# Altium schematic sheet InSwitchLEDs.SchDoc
size A4; SheetNumber: 2; SheetTotal: 2
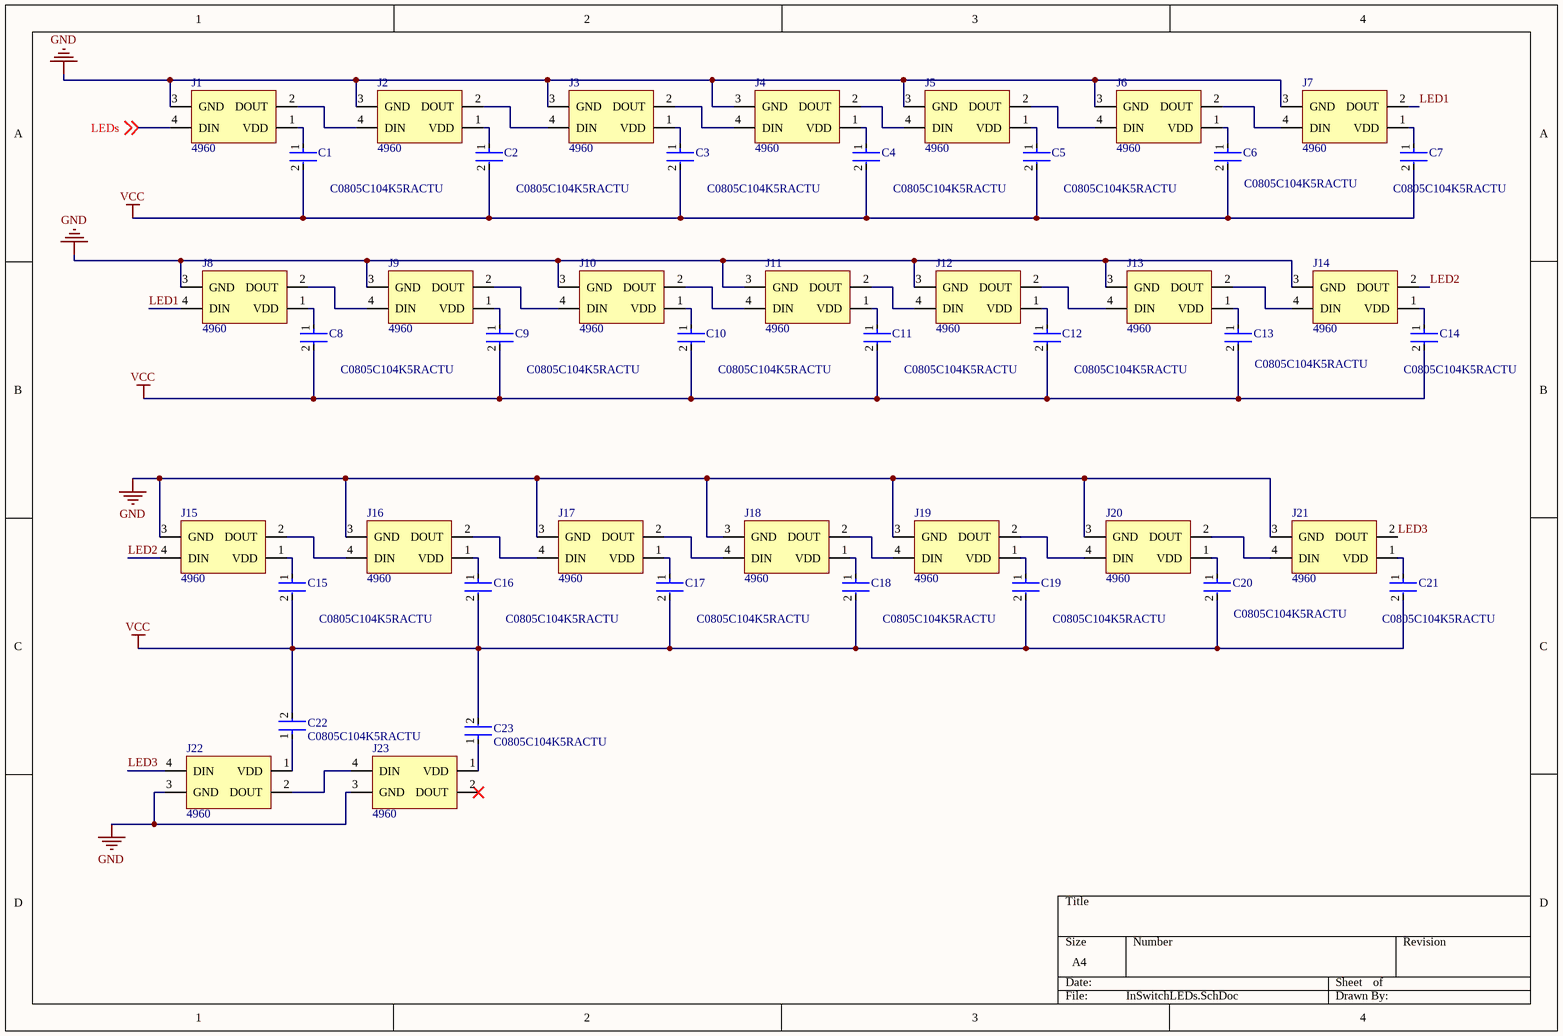
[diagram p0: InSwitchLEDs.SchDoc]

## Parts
C1  C0805C104K5RACTU  [FP-C0805C-DN-MFG]
C2  C0805C104K5RACTU  [FP-C0805C-DN-MFG]
C3  C0805C104K5RACTU  [FP-C0805C-DN-MFG]
C4  C0805C104K5RACTU  [FP-C0805C-DN-MFG]
C5  C0805C104K5RACTU  [FP-C0805C-DN-MFG]
C6  C0805C104K5RACTU  [FP-C0805C-DN-MFG]
C7  C0805C104K5RACTU  [FP-C0805C-DN-MFG]
C8  C0805C104K5RACTU  [FP-C0805C-DN-MFG]
C9  C0805C104K5RACTU  [FP-C0805C-DN-MFG]
C10  C0805C104K5RACTU  [FP-C0805C-DN-MFG]
C11  C0805C104K5RACTU  [FP-C0805C-DN-MFG]
C12  C0805C104K5RACTU  [FP-C0805C-DN-MFG]
C13  C0805C104K5RACTU  [FP-C0805C-DN-MFG]
C14  C0805C104K5RACTU  [FP-C0805C-DN-MFG]
C15  C0805C104K5RACTU  [FP-C0805C-DN-MFG]
C16  C0805C104K5RACTU  [FP-C0805C-DN-MFG]
C17  C0805C104K5RACTU  [FP-C0805C-DN-MFG]
C18  C0805C104K5RACTU  [FP-C0805C-DN-MFG]
C19  C0805C104K5RACTU  [FP-C0805C-DN-MFG]
C20  C0805C104K5RACTU  [FP-C0805C-DN-MFG]
C21  C0805C104K5RACTU  [FP-C0805C-DN-MFG]
C22  C0805C104K5RACTU  [FP-C0805C-DN-MFG]
C23  C0805C104K5RACTU  [FP-C0805C-DN-MFG]
J1  4960  [4960_Adafruit]
J2  4960  [4960_Adafruit]
J3  4960  [4960_Adafruit]
J4  4960  [4960_Adafruit]
J5  4960  [4960_Adafruit]
J6  4960  [4960_Adafruit]
J7  4960  [4960_Adafruit]
J8  4960  [4960_Adafruit]
J9  4960  [4960_Adafruit]
J10  4960  [4960_Adafruit]
J11  4960  [4960_Adafruit]
J12  4960  [4960_Adafruit]
J13  4960  [4960_Adafruit]
J14  4960  [4960_Adafruit]
J15  4960  [4960_Adafruit]
J16  4960  [4960_Adafruit]
J17  4960  [4960_Adafruit]
J18  4960  [4960_Adafruit]
J19  4960  [4960_Adafruit]
J20  4960  [4960_Adafruit]
J21  4960  [4960_Adafruit]
J22  4960  [4960_Adafruit]
J23  4960  [4960_Adafruit]

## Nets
GND: J1.3(GND) J2.3(GND) J3.3(GND) J4.3(GND) J5.3(GND) J6.3(GND) J7.3(GND) J8.3(GND) J9.3(GND) J10.3(GND) J11.3(GND) J12.3(GND) J13.3(GND) J14.3(GND) J15.3(GND) J16.3(GND) J17.3(GND) J18.3(GND) J19.3(GND) J20.3(GND) J21.3(GND) J22.3(GND) J23.3(GND)
VCC: C1.2 C2.2 C3.2 C4.2 C5.2 C6.2 C7.2 C8.2 C9.2 C10.2 C11.2 C12.2 C13.2 C14.2 C15.2 C16.2 C17.2 C18.2 C19.2 C20.2 C21.2 C22.2 C23.2
LED1: J7.2(DOUT) J8.4(DIN)
LED2: J14.2(DOUT) J15.4(DIN)
LED3: J21.2(DOUT) J22.4(DIN)
LEDs: J1.4(DIN) ; off-sheet LEDs
NetC1_1: C1.1 J1.1(VDD)
NetC2_1: C2.1 J2.1(VDD)
NetC3_1: C3.1 J3.1(VDD)
NetC4_1: C4.1 J4.1(VDD)
NetC5_1: C5.1 J5.1(VDD)
NetC6_1: C6.1 J6.1(VDD)
NetC7_1: C7.1 J7.1(VDD)
NetC8_1: C8.1 J8.1(VDD)
NetC9_1: C9.1 J9.1(VDD)
NetC10_1: C10.1 J10.1(VDD)
NetC11_1: C11.1 J11.1(VDD)
NetC12_1: C12.1 J12.1(VDD)
NetC13_1: C13.1 J13.1(VDD)
NetC14_1: C14.1 J14.1(VDD)
NetC15_1: C15.1 J15.1(VDD)
NetC16_1: C16.1 J16.1(VDD)
NetC17_1: C17.1 J17.1(VDD)
NetC18_1: C18.1 J18.1(VDD)
NetC19_1: C19.1 J19.1(VDD)
NetC20_1: C20.1 J20.1(VDD)
NetC21_1: C21.1 J21.1(VDD)
NetC22_1: C22.1 J22.1(VDD)
NetC23_1: C23.1 J23.1(VDD)
NetJ1_2: J1.2(DOUT) J2.4(DIN)
NetJ2_2: J2.2(DOUT) J3.4(DIN)
NetJ3_2: J3.2(DOUT) J4.4(DIN)
NetJ4_2: J4.2(DOUT) J5.4(DIN)
NetJ5_2: J5.2(DOUT) J6.4(DIN)
NetJ6_2: J6.2(DOUT) J7.4(DIN)
NetJ8_2: J8.2(DOUT) J9.4(DIN)
NetJ9_2: J9.2(DOUT) J10.4(DIN)
NetJ10_2: J10.2(DOUT) J11.4(DIN)
NetJ11_2: J11.2(DOUT) J12.4(DIN)
NetJ12_2: J12.2(DOUT) J13.4(DIN)
NetJ13_2: J13.2(DOUT) J14.4(DIN)
NetJ15_2: J15.2(DOUT) J16.4(DIN)
NetJ16_2: J16.2(DOUT) J17.4(DIN)
NetJ17_2: J17.2(DOUT) J18.4(DIN)
NetJ18_2: J18.2(DOUT) J19.4(DIN)
NetJ19_2: J19.2(DOUT) J20.4(DIN)
NetJ20_2: J20.2(DOUT) J21.4(DIN)
NetJ22_2: J22.2(DOUT) J23.4(DIN)

Not connected (* = marked no-connect by the designer): J23 2(DOUT)*

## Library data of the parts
C1-C23 = CMP-2007-00279-2: CAP CER 0.1UF 50V X7R 0805; Manufacturer: KEMET; Value: 0.10 μF; Tolerance: 0.1; Temperature Coefficient: 30ppm/°C; Material: Ceramic
J1-J23 = Component_1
